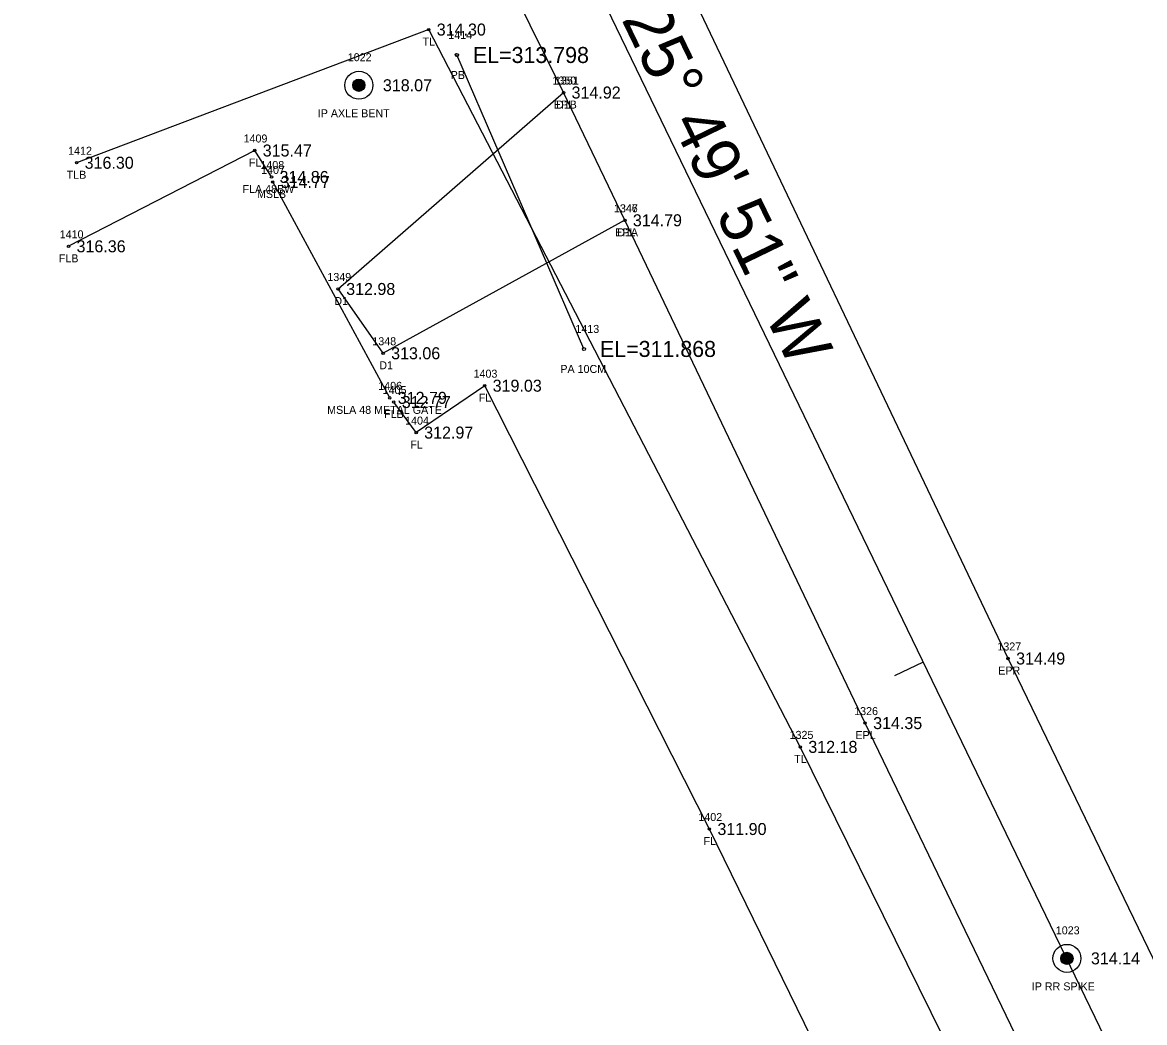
# Model space of a CAD drawing. Extents: x 1865045 to 1867370, y 910391 to 914218.
# Drawn here: x 1866074.6 to 1866214.8, y 911443.2 to 911568.1 of the extents above; entities that cross this region are included whole.
import ezdxf

# ---------------------------------------------------------------- set-up
doc = ezdxf.new("R2010")
doc.units = 0
for name, color, linetype in [('RD_EX_DR_Pipe', 7, 'Continuous'), ('RD_EX_DR_Pipe_txCode', 7, 'Continuous'), ('RD_EX_Driveway', 7, 'Continuous'), ('RD_EX_Driveway_txCode', 7, 'Continuous'), ('RD_EX_DV_Prop_txCode', 7, 'Continuous'), ('RD_EX_DV_PropPin', 7, 'Continuous'), ('RD_EX_Fence_Other', 7, 'Continuous'), ('RD_EX_Fence_Other_txCode', 7, 'Continuous'), ('RD_EX_Misc', 7, 'Continuous'), ('RD_EX_Misc_txCode', 7, 'Continuous'), ('RD_EX_Road', 7, 'Continuous'), ('RD_EX_Road_txCode', 7, 'Continuous'), ('RD_EX_TX_Driveway_ELEV', 7, 'Continuous'), ('RD_EX_TX_DV_Prop_ELEV', 7, 'Continuous'), ('RD_EX_TX_Fence_Other_ELEV', 7, 'Continuous'), ('RD_EX_TX_Misc_ELEV', 7, 'Continuous'), ('RD_EX_TX_Road_ELEV', 7, 'Continuous'), ('RD_EX_TX_VEG_ELEV', 7, 'Continuous'), ('RD_EX_VEG', 7, 'Continuous'), ('RD_EX_VEG_txCode', 7, 'Continuous'), ('RD_HC_Cl', 7, 'Continuous'), ('RD_HC_Data', 7, 'Continuous'), ('RD_HC_Data_Tic', 7, 'Continuous'), ('RD_SMD_Locator', 7, 'Continuous'), ('RD_TX_Pipe_ElevEX', 7, 'Continuous')]:
    doc.layers.add(name, color=color, linetype=linetype)

msp = doc.modelspace()

# ---------------------------------------------------------------- linework, layer by layer
at = {"layer": 'RD_EX_DR_Pipe'}
msp.add_line((1866144.73, 911527.34), (1866128.85, 911564.06), dxfattribs=at)
at = {"layer": 'RD_EX_Driveway'}
msp.add_lwpolyline([(1866149.84, 911543.41), (1866119.63, 911526.8), (1866114.01, 911534.83), (1866142.18, 911559.37)], dxfattribs=at)
at = {"layer": 'RD_EX_DV_PropPin'}
for p, q in [((1866115.9, 911559.99), (1866115.9, 911560.58)), ((1866115.94, 911559.92), (1866115.94, 911560.65)), ((1866115.97, 911559.86), (1866115.97, 911560.71)), ((1866116.01, 911559.81), (1866116.01, 911560.76)), ((1866116.04, 911559.77), (1866116.04, 911560.8)), ((1866116.08, 911559.73), (1866116.08, 911560.84)), ((1866116.11, 911559.7), (1866116.11, 911560.87)), ((1866116.15, 911559.68), (1866116.15, 911560.89)), ((1866116.18, 911559.65), (1866116.18, 911560.92)), ((1866116.22, 911559.63), (1866116.22, 911560.94)), ((1866116.25, 911559.61), (1866116.25, 911560.96)), ((1866116.29, 911559.59), (1866116.29, 911560.98)), ((1866116.32, 911559.58), (1866116.32, 911560.99)), ((1866116.36, 911559.56), (1866116.36, 911561.01)), ((1866116.39, 911559.55), (1866116.39, 911561.02)), ((1866116.43, 911559.54), (1866116.43, 911561.03)), ((1866116.46, 911559.54), (1866116.46, 911561.03)), ((1866116.5, 911559.53), (1866116.5, 911561.04)), ((1866116.53, 911559.53), (1866116.53, 911561.04)), ((1866116.57, 911559.52), (1866116.57, 911561.05)), ((1866116.6, 911559.52), (1866116.6, 911561.05)), ((1866116.64, 911559.52), (1866116.64, 911561.05)), ((1866116.67, 911559.53), (1866116.67, 911561.04)), ((1866116.71, 911559.53), (1866116.71, 911561.04)), ((1866116.74, 911559.54), (1866116.74, 911561.03)), ((1866116.78, 911559.54), (1866116.78, 911561.03)), ((1866116.81, 911559.55), (1866116.81, 911561.02)), ((1866116.85, 911559.56), (1866116.85, 911561.01)), ((1866116.88, 911559.58), (1866116.88, 911560.99)), ((1866116.92, 911559.59), (1866116.92, 911560.98)), ((1866116.95, 911559.61), (1866116.95, 911560.96)), ((1866116.99, 911559.63), (1866116.99, 911560.94)), ((1866117.02, 911559.65), (1866117.02, 911560.92)), ((1866117.06, 911559.68), (1866117.06, 911560.89)), ((1866117.09, 911559.7), (1866117.09, 911560.87)), ((1866117.13, 911559.73), (1866117.13, 911560.84)), ((1866117.16, 911559.77), (1866117.16, 911560.8)), ((1866117.2, 911559.81), (1866117.2, 911560.76)), ((1866117.23, 911559.86), (1866117.23, 911560.71)), ((1866117.27, 911559.92), (1866117.27, 911560.65)), ((1866117.3, 911559.99), (1866117.3, 911560.58)), ((1866115.87, 911560.09), (1866115.87, 911560.48)), ((1866117.34, 911560.09), (1866117.34, 911560.48)), ((1866204.36, 911451.01), (1866204.36, 911451.41)), ((1866204.39, 911450.91), (1866204.39, 911451.51)), ((1866204.43, 911450.84), (1866204.43, 911451.58)), ((1866204.46, 911450.78), (1866204.46, 911451.64)), ((1866204.5, 911450.74), (1866204.5, 911451.68)), ((1866204.53, 911450.69), (1866204.53, 911451.72)), ((1866204.57, 911450.66), (1866204.57, 911451.76)), ((1866204.6, 911450.63), (1866204.6, 911451.79)), ((1866204.64, 911450.6), (1866204.64, 911451.82)), ((1866204.67, 911450.57), (1866204.67, 911451.84)), ((1866204.71, 911450.55), (1866204.71, 911451.87)), ((1866204.74, 911450.53), (1866204.74, 911451.89)), ((1866204.78, 911450.52), (1866204.78, 911451.9)), ((1866204.81, 911450.5), (1866204.81, 911451.92)), ((1866204.85, 911450.49), (1866204.85, 911451.93)), ((1866204.88, 911450.48), (1866204.88, 911451.94)), ((1866204.92, 911450.47), (1866204.92, 911451.95)), ((1866204.95, 911450.46), (1866204.95, 911451.96)), ((1866204.99, 911450.46), (1866204.99, 911451.96)), ((1866205.02, 911450.45), (1866205.02, 911451.97)), ((1866205.06, 911450.45), (1866205.06, 911451.97)), ((1866205.09, 911450.45), (1866205.09, 911451.97)), ((1866205.13, 911450.45), (1866205.13, 911451.97)), ((1866205.16, 911450.45), (1866205.16, 911451.97)), ((1866205.2, 911450.46), (1866205.2, 911451.96)), ((1866205.23, 911450.46), (1866205.23, 911451.96)), ((1866205.27, 911450.47), (1866205.27, 911451.95)), ((1866205.3, 911450.48), (1866205.3, 911451.94)), ((1866205.34, 911450.49), (1866205.34, 911451.93)), ((1866205.37, 911450.5), (1866205.37, 911451.92)), ((1866205.41, 911450.52), (1866205.41, 911451.9)), ((1866205.44, 911450.53), (1866205.44, 911451.89)), ((1866205.48, 911450.55), (1866205.48, 911451.87)), ((1866205.51, 911450.57), (1866205.51, 911451.84)), ((1866205.55, 911450.6), (1866205.55, 911451.82)), ((1866205.58, 911450.63), (1866205.58, 911451.79)), ((1866205.62, 911450.66), (1866205.62, 911451.76)), ((1866205.65, 911450.69), (1866205.65, 911451.72)), ((1866205.69, 911450.74), (1866205.69, 911451.68)), ((1866205.72, 911450.78), (1866205.72, 911451.64)), ((1866205.76, 911450.84), (1866205.76, 911451.58)), ((1866205.79, 911450.91), (1866205.79, 911451.51)), ((1866205.83, 911451.01), (1866205.83, 911451.41))]:
    msp.add_line(p, q, dxfattribs=at)
for centre, radius in [((1866116.6, 911560.28), 1.75), ((1866116.6, 911560.28), 0.761), ((1866205.09, 911451.21), 1.75), ((1866205.09, 911451.21), 0.761)]:
    msp.add_circle(centre, radius, dxfattribs=at)
at = {"layer": 'RD_EX_Fence_Other'}
for points in [[(1866105.68, 911548.82), (1866103.58, 911552.13), (1866080.31, 911540.16)], [(1866328.11, 911123.98), (1866317.73, 911143.27), (1866292.21, 911196.64), (1866254.72, 911273.66), (1866198.8, 911388.88), (1866160.41, 911467.37), (1866132.32, 911522.75), (1866123.76, 911516.89), (1866120.96, 911520.71)]]:
    msp.add_lwpolyline(points, dxfattribs=at)
at = {"layer": 'RD_EX_Misc'}
msp.add_line((1866120.46, 911521.23), (1866105.83, 911548.2), dxfattribs=at)
at = {"layer": 'RD_EX_Road'}
for points in [[(1866367.09, 911115.22), (1866376.17, 911119.76), (1866330.4, 911213.7), (1866286.92, 911304.16), (1866242.4, 911396.3), (1866197.74, 911488.67), (1866154.31, 911579.91), (1866143.08, 911603.17), (1866108.16, 911674.25), (1866059.64, 911774.84), (1866048.38, 911798.67), (1866045.99, 911803.62)], [(1866367.09, 911115.22), (1866357.99, 911110.97), (1866313.12, 911203.44), (1866268.86, 911295.9), (1866224.24, 911388.66), (1866179.87, 911480.6), (1866149.84, 911543.41), (1866142.18, 911559.37), (1866135.93, 911572.05), (1866096.83, 911651.51), (1866089.65, 911665.46), (1866062.87, 911720.39), (1866042.14, 911765.69), (1866027.93, 911795.04)]]:
    msp.add_lwpolyline(points, dxfattribs=at)
at = {"layer": 'RD_EX_VEG'}
msp.add_lwpolyline([(1866452.86, 910898.44), (1866327.79, 911152.66), (1866304.37, 911199.34), (1866261.27, 911293.31), (1866216.38, 911387.21), (1866171.77, 911477.63), (1866125.33, 911567.24), (1866081.32, 911550.6)], dxfattribs=at)
at = {"layer": 'RD_HC_Cl'}
msp.add_line((1866280.52, 911295.32), (1866034.98, 911802.56), dxfattribs=at)
at = {"layer": 'RD_HC_Data_Tic'}
msp.add_line((1866187.14, 911488.23), (1866183.54, 911486.49), dxfattribs=at)
at = {"layer": 'RD_SMD_Locator'}
for centre, radius in [((1866125.33, 911567.24), 0.15), ((1866128.85, 911564.06), 0.2), ((1866116.6, 911560.28), 0.15), ((1866142.18, 911559.37), 0.15), ((1866142.18, 911559.37), 0.15), ((1866103.58, 911552.13), 0.15), ((1866081.32, 911550.6), 0.15), ((1866105.68, 911548.82), 0.15), ((1866105.83, 911548.2), 0.15), ((1866149.84, 911543.41), 0.15), ((1866149.84, 911543.41), 0.15), ((1866080.31, 911540.16), 0.15), ((1866114.01, 911534.83), 0.15), ((1866119.63, 911526.8), 0.15), ((1866144.73, 911527.34), 0.2), ((1866132.32, 911522.75), 0.15), ((1866120.46, 911521.23), 0.15), ((1866120.96, 911520.71), 0.15), ((1866123.76, 911516.89), 0.15), ((1866197.74, 911488.67), 0.15), ((1866179.87, 911480.6), 0.15), ((1866171.77, 911477.63), 0.15), ((1866160.41, 911467.37), 0.15), ((1866205.09, 911451.21), 0.15)]:
    msp.add_circle(centre, radius, dxfattribs=at)

# ---------------------------------------------------------------- texts
at = {"layer": 'RD_EX_DR_Pipe_txCode'}
for s, p in [('1414', (1866127.78, 911566.06)), ('PB', (1866128.07, 911561.06)), ('1413', (1866143.66, 911529.34)), ('PA 10CM', (1866141.78, 911524.34))]:
    msp.add_text(s, height=1, dxfattribs=at).set_placement(p)
at = {"layer": 'RD_EX_Driveway_txCode'}
for s, p in [('1350', (1866140.79, 911560.37)), ('D1B', (1866141.23, 911557.37)), ('1347', (1866148.49, 911544.41)), ('D1A', (1866148.88, 911541.41)), ('1349', (1866112.66, 911535.83)), ('D1', (1866113.53, 911532.83)), ('1348', (1866118.28, 911527.8)), ('D1', (1866119.15, 911524.8))]:
    msp.add_text(s, height=1, dxfattribs=at).set_placement(p)
at = {"layer": 'RD_EX_DV_Prop_txCode'}
for s, p in [('1022', (1866115.21, 911563.28)), ('IP AXLE BENT', (1866111.46, 911556.28)), ('1023', (1866203.7, 911454.21)), ('IP RR SPIKE', (1866200.7, 911447.21))]:
    msp.add_text(s, height=1, dxfattribs=at).set_placement(p)
at = {"layer": 'RD_EX_Fence_Other_txCode'}
for s, p in [('1409', (1866102.19, 911553.13)), ('FL', (1866102.85, 911550.13)), ('1408', (1866104.29, 911549.82)), ('FLA 48BW', (1866102.06, 911546.82)), ('1410', (1866079.21, 911541.16)), ('FLB', (1866079.1, 911538.16)), ('1403', (1866130.93, 911523.75)), ('1405', (1866119.57, 911521.71)), ('FL', (1866131.58, 911520.75)), ('FLB', (1866119.75, 911518.71)), ('1404', (1866122.38, 911517.89)), ('FL', (1866123.03, 911514.89)), ('1402', (1866159.03, 911468.37)), ('FL', (1866159.68, 911465.37))]:
    msp.add_text(s, height=1, dxfattribs=at).set_placement(p)
at = {"layer": 'RD_EX_Misc_txCode'}
for s, p in [('1407', (1866104.38, 911549.2)), ('MSLB', (1866103.86, 911546.2)), ('1406', (1866119.02, 911522.23)), ('MSLA 48 METAL GATE', (1866112.63, 911519.23))]:
    msp.add_text(s, height=1, dxfattribs=at).set_placement(p)
at = {"layer": 'RD_EX_Road_txCode'}
for s, p in [('1351', (1866141.12, 911560.37)), ('EPL', (1866140.97, 911557.37)), ('1346', (1866148.47, 911544.41)), ('EPL', (1866148.63, 911541.41)), ('1327', (1866196.4, 911489.67)), ('EPR', (1866196.51, 911486.67)), ('1326', (1866178.5, 911481.6)), ('EPL', (1866178.66, 911478.6))]:
    msp.add_text(s, height=1, dxfattribs=at).set_placement(p)
at = {"layer": 'RD_EX_TX_Driveway_ELEV'}
for s, p in [('314.92', (1866143.18, 911558.62)), ('314.79', (1866150.84, 911542.66)), ('312.98', (1866115.01, 911534.08)), ('313.06', (1866120.63, 911526.05))]:
    msp.add_text(s, height=1.5, dxfattribs=at).set_placement(p)
at = {"layer": 'RD_EX_TX_DV_Prop_ELEV'}
for s, p in [('318.07', (1866119.6, 911559.53)), ('314.14', (1866208.09, 911450.46))]:
    msp.add_text(s, height=1.5, dxfattribs=at).set_placement(p)
at = {"layer": 'RD_EX_TX_Fence_Other_ELEV'}
for s, p in [('315.47', (1866104.58, 911551.38)), ('314.86', (1866106.68, 911548.07)), ('316.36', (1866081.31, 911539.41)), ('319.03', (1866133.32, 911522)), ('312.77', (1866121.96, 911519.96)), ('312.97', (1866124.76, 911516.14)), ('311.90', (1866161.41, 911466.62))]:
    msp.add_text(s, height=1.5, dxfattribs=at).set_placement(p)
at = {"layer": 'RD_EX_TX_Misc_ELEV'}
for s, p in [('314.77', (1866106.83, 911547.45)), ('312.79', (1866121.46, 911520.48))]:
    msp.add_text(s, height=1.5, dxfattribs=at).set_placement(p)
at = {"layer": 'RD_EX_TX_Road_ELEV'}
for s, p in [('314.92', (1866143.18, 911558.62)), ('314.79', (1866150.84, 911542.66)), ('314.49', (1866198.74, 911487.92)), ('314.35', (1866180.87, 911479.85))]:
    msp.add_text(s, height=1.5, dxfattribs=at).set_placement(p)
at = {"layer": 'RD_EX_TX_VEG_ELEV'}
for s, p in [('314.30', (1866126.33, 911566.49)), ('316.30', (1866082.32, 911549.85)), ('312.18', (1866172.77, 911476.88))]:
    msp.add_text(s, height=1.5, dxfattribs=at).set_placement(p)
at = {"layer": 'RD_EX_VEG_txCode'}
for s, p in [('TL', (1866124.56, 911565.24)), ('1412', (1866080.26, 911551.6)), ('TLB', (1866080.08, 911548.6)), ('1325', (1866170.43, 911478.63)), ('TL', (1866171, 911475.63))]:
    msp.add_text(s, height=1, dxfattribs=at).set_placement(p)
at = {"layer": 'RD_HC_Data'}
msp.add_text('N 25%%d 49\' 51" W', height=6, rotation=295.8309, dxfattribs=at).set_placement((1866145.87, 911575.76))
at = {"layer": 'RD_TX_Pipe_ElevEX'}
for s, p in [('EL=313.798', (1866130.85, 911563.06)), ('EL=311.868', (1866146.73, 911526.34))]:
    msp.add_text(s, height=2, dxfattribs=at).set_placement(p)

doc.saveas('drawing.dxf')
